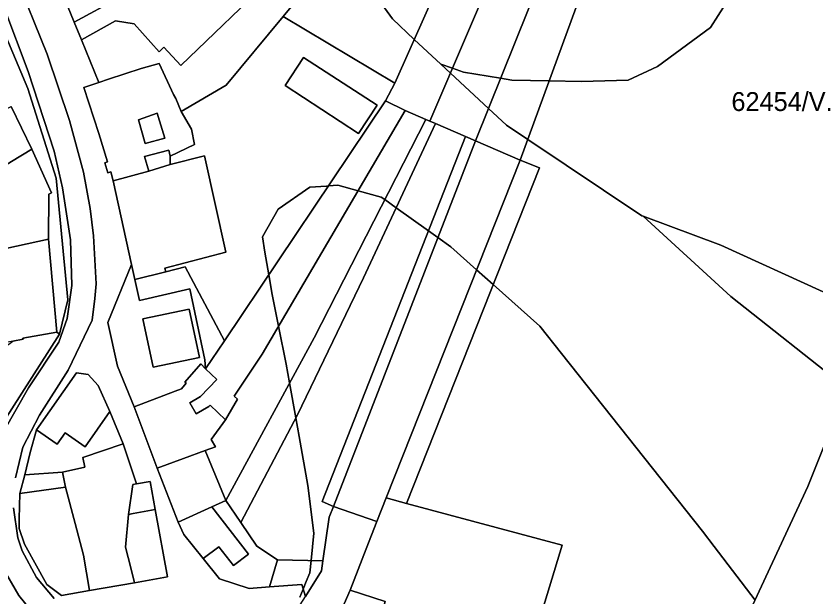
# Model space of a CAD drawing. Extents: x -522079 to -518833, y -1142400 to -1139961.
# Drawn here: x -520338.9 to -520127.5, y -1141173.1 to -1141019.5 of the extents above; entities that cross this region are included whole.
import ezdxf

# ---------------------------------------------------------------- set-up
doc = ezdxf.new("R2010")
doc.units = 0
for name, color, linetype in [('95560013', 7, 'Continuous'), ('95590013', 7, 'Continuous'), ('95640013', 7, 'Continuous'), ('95660013', 7, 'Continuous')]:
    doc.layers.add(name, color=color, linetype=linetype)

msp = doc.modelspace()

# ---------------------------------------------------------------- linework, layer by layer
at = {"layer": '95560013'}
for points in [[(-520205.51, -1141057.7), (-520170.88, -1140963.13), (-520079.53, -1141019.58), (-520129.38, -1141144.09), (-520158.56, -1141206.98), (-520178.85, -1141202.22), (-520209, -1141207.86), (-520194.38, -1141159.65), (-520235.62, -1141148.58), (-520200.4, -1141059.73)], [(-520079.53, -1141019.58), (-520032.33, -1141047.7), (-519951.21, -1141077.01), (-519948.1, -1141084.44), (-519980.55, -1141165.39), (-520014.17, -1141252.24), (-520020.92, -1141254.2), (-520158.56, -1141206.98), (-520129.38, -1141144.09)]]:
    msp.add_lwpolyline(points, close=True, dxfattribs=at)
at = {"layer": '95590013'}
for points in [[(-520278.46, -1140964.1), (-520294.61, -1140946.2), (-520299.04, -1140950.24), (-520300.74, -1140948.36), (-520257.36, -1140921.21), (-520246.32, -1140932.55), (-520237.12, -1140923.52), (-520250.18, -1140910.34), (-520199.46, -1140857.65), (-520181.95, -1140869.32), (-520182.55, -1140869.96), (-520164.55, -1140881.96), (-520151.68, -1140896.26), (-520156.19, -1140899.86), (-520180.26, -1140950.09), (-520199.25, -1140950.43), (-520200.79, -1140952.24), (-520238.67, -1141037.33), (-520268.23, -1141019.69), (-520245.17, -1140991.88)], [(-520235.95, -1141044.56), (-520241.17, -1141042.05), (-520238.67, -1141037.33), (-520200.79, -1140952.24), (-520189.01, -1140952.86), (-520229.4, -1141047.39), (-520230.46, -1141046.93)], [(-520181.77, -1140953.24), (-520178.74, -1140956.58), (-520217.35, -1141052.59), (-520219.97, -1141051.46), (-520227.89, -1141048.04), (-520229.4, -1141047.39), (-520189.01, -1140952.86)], [(-520217.35, -1141052.59), (-520178.74, -1140956.58), (-520175.23, -1140960.44), (-520170.88, -1140963.13), (-520205.51, -1141057.7)], [(-520291.66, -1141053.56), (-520292.48, -1141049.55), (-520295.18, -1141044.79), (-520283.27, -1141037.84), (-520268.23, -1141019.69), (-520238.67, -1141037.33), (-520241.17, -1141042.05), (-520283.75, -1141105.56), (-520294.2, -1141085.93), (-520299.29, -1141087.24), (-520299.54, -1141086.27), (-520283.36, -1141082.1), (-520289.01, -1141056.56), (-520298.12, -1141058.85), (-520298.11, -1141056.69)], [(-520262.81, -1141030.49), (-520267.66, -1141037.99), (-520248.33, -1141050.65), (-520243.34, -1141043.16)], [(-520280.3, -1141121.02), (-520283.49, -1141126.48), (-520287.59, -1141122.55), (-520287.92, -1141122.9), (-520291.23, -1141124.89), (-520292.95, -1141121.95), (-520290.1, -1141120.29), (-520285.76, -1141115.8), (-520288.75, -1141112.92), (-520283.75, -1141105.56), (-520241.17, -1141042.05), (-520235.95, -1141044.56), (-520273.79, -1141109.04), (-520281.17, -1141120.23)], [(-520288.84, -1141134.57), (-520286.17, -1141133.59), (-520287.28, -1141131.69), (-520283.49, -1141126.48), (-520280.3, -1141121.02), (-520281.17, -1141120.23), (-520273.79, -1141109.04), (-520235.95, -1141044.56), (-520230.46, -1141046.93), (-520260.05, -1141104.78), (-520283.41, -1141147.79)], [(-520229.4, -1141047.39), (-520227.89, -1141048.04), (-520246.96, -1141088.89), (-520264.44, -1141125.14), (-520279.46, -1141153.62), (-520283.41, -1141147.79), (-520260.05, -1141104.78), (-520230.46, -1141046.93)], [(-520264.44, -1141125.14), (-520246.96, -1141088.89), (-520227.89, -1141048.04), (-520219.97, -1141051.46), (-520257.88, -1141148.13), (-520254.95, -1141149.39), (-520256.03, -1141152.27), (-520257.71, -1141163.82), (-520269.77, -1141163.56), (-520275.19, -1141159.91), (-520279.46, -1141153.62)], [(-520205.51, -1141057.7), (-520240.94, -1141147.15), (-520243.41, -1141153.37), (-520254.95, -1141149.39), (-520217.35, -1141052.59)], [(-520200.4, -1141059.73), (-520235.62, -1141148.58), (-520240.94, -1141147.15), (-520205.51, -1141057.7)], [(-520309.19, -1141151.52), (-520308.03, -1141143.58), (-520307.07, -1141143.41), (-520303.47, -1141142.76), (-520302.11, -1141150.23), (-520307.91, -1141151.29)], [(-520275.19, -1141159.91), (-520269.77, -1141163.56), (-520271.87, -1141170.72), (-520277.22, -1141171.12), (-520285.07, -1141168.6), (-520289.43, -1141163.17), (-520285.21, -1141160.06), (-520281.38, -1141165.06), (-520277.44, -1141162.04), (-520287.07, -1141149.47), (-520283.41, -1141147.79), (-520279.46, -1141153.62)], [(-520209, -1141207.86), (-520222.29, -1141209.66), (-520219.73, -1141201.41), (-520215.84, -1141187.57), (-520242.23, -1141179.94), (-520242.77, -1141179.78), (-520241.26, -1141174.54), (-520250.48, -1141171.53), (-520246.26, -1141160.66), (-520243.41, -1141153.37), (-520240.94, -1141147.15), (-520235.62, -1141148.58), (-520194.38, -1141159.65)], [(-520243.41, -1141153.37), (-520246.26, -1141160.66), (-520250.48, -1141171.53), (-520253.97, -1141179.43), (-520255.51, -1141182.9), (-520257.33, -1141187.03), (-520257.63, -1141187.7), (-520267.83, -1141182.58), (-520262.19, -1141185.29), (-520260.45, -1141181.87), (-520258.53, -1141178.07), (-520263.7, -1141175.46), (-520262.34, -1141173.28), (-520258.09, -1141166.43), (-520257.71, -1141163.82), (-520256.03, -1141152.27), (-520254.95, -1141149.39)], [(-520241.26, -1141174.54), (-520242.77, -1141179.78), (-520243.9, -1141183.68), (-520253.97, -1141179.43), (-520250.48, -1141171.53)]]:
    msp.add_lwpolyline(points, close=True, dxfattribs=at)
msp.add_lwpolyline([(-520245.17, -1140991.88), (-520268.23, -1141019.69), (-520283.27, -1141037.84), (-520295.18, -1141044.79), (-520296.61, -1141041.42), (-520297.24, -1141040.29), (-520301.05, -1141032.14), (-520305.82, -1141033.42), (-520314.43, -1141036.29), (-520317.01, -1141037.16), (-520321.6, -1141025.87), (-520312.58, -1141020.86), (-520307.7, -1141021.63), (-520301.02, -1141029.07), (-520299.78, -1141027.82), (-520295.32, -1141032.65), (-520270.67, -1141008.89)], dxfattribs=at)
at = {"layer": '95640013'}
for points in [[(-520371.53, -1140953.82), (-520335.76, -1141038.73), (-520328.34, -1141062.52), (-520325.25, -1141094.67), (-520327.42, -1141103.8), (-520328.09, -1141103.27), (-520330.35, -1141078.64), (-520330.22, -1141066.74), (-520329.51, -1141066.36), (-520334.74, -1141054.84), (-520340.18, -1141043.47)], [(-520344.78, -1141130.88), (-520327.42, -1141103.8), (-520325.25, -1141094.67), (-520328.34, -1141062.52), (-520335.76, -1141038.73), (-520371.53, -1140953.82)], [(-520339.2, -1141008.34), (-520330.66, -1141029.65), (-520324.76, -1141047.17), (-520321.07, -1141060.89), (-520319.27, -1141070.53), (-520318.44, -1141077.73), (-520317.76, -1141090.48), (-520318.04, -1141094.37), (-520318.78, -1141100.08), (-520325.12, -1141113.35), (-520332.74, -1141125.19), (-520337.15, -1141133.73), (-520339.09, -1141141.84)], [(-520339.09, -1141141.84), (-520337.15, -1141133.73), (-520332.74, -1141125.19), (-520325.12, -1141113.35), (-520318.78, -1141100.08), (-520318.04, -1141094.37), (-520317.76, -1141090.48), (-520318.44, -1141077.73), (-520319.27, -1141070.53), (-520321.07, -1141060.89), (-520324.76, -1141047.17), (-520330.66, -1141029.65), (-520339.2, -1141008.34)], [(-520328.8, -1141008.12), (-520323.52, -1141021.14), (-520321.6, -1141025.87), (-520317.01, -1141037.16), (-520320.97, -1141038.48), (-520317.05, -1141050.62), (-520314.7, -1141058.15), (-520315.46, -1141058.39), (-520314.63, -1141061.07), (-520313.88, -1141060.82), (-520313.18, -1141063.23), (-520308.39, -1141085.31), (-520314.66, -1141100.66), (-520312.08, -1141112.23), (-520307.67, -1141123.05), (-520305.82, -1141127.93), (-520301.56, -1141139.26), (-520296.03, -1141153.59), (-520294.54, -1141156.83), (-520289.43, -1141163.17), (-520285.07, -1141168.6), (-520277.22, -1141171.12), (-520271.87, -1141170.72), (-520263.33, -1141170.08), (-520262.34, -1141173.28)], [(-520342.14, -1141129.51), (-520335.59, -1141118), (-520327.56, -1141105.89), (-520325.35, -1141099.6), (-520324.16, -1141090.88), (-520324.51, -1141078.81), (-520326.63, -1141065), (-520328.86, -1141055.37), (-520335.75, -1141034.28), (-520342.18, -1141017.11)], [(-520342.18, -1141017.11), (-520335.75, -1141034.28), (-520328.86, -1141055.37), (-520326.63, -1141065), (-520324.51, -1141078.81), (-520324.16, -1141090.88), (-520325.35, -1141099.6), (-520327.56, -1141105.89), (-520335.59, -1141118), (-520342.14, -1141129.51)], [(-520425.27, -1141175.41), (-520408.18, -1141157.48), (-520397.97, -1141139.24), (-520387.46, -1141120.02), (-520366.58, -1141115.24), (-520361.02, -1141115.3), (-520345.24, -1141109.63), (-520339.78, -1141105.62), (-520337.04, -1141105.09), (-520337.09, -1141104.85), (-520328.09, -1141103.27), (-520327.42, -1141103.8), (-520344.78, -1141130.88), (-520344.38, -1141136.25), (-520345.84, -1141145.82), (-520345.14, -1141156.25), (-520343.69, -1141161.58), (-520342.68, -1141165.24), (-520338.22, -1141172.95), (-520335.19, -1141176.69)], [(-520339.64, -1141149.76), (-520338.41, -1141157.75), (-520337.34, -1141161.13), (-520333.5, -1141168.21), (-520328.85, -1141173.77)], [(-520328.85, -1141173.77), (-520333.5, -1141168.21), (-520337.34, -1141161.13), (-520338.41, -1141157.75), (-520339.64, -1141149.76)], [(-520335.19, -1141176.69), (-520338.22, -1141172.95), (-520342.68, -1141165.24)]]:
    msp.add_lwpolyline(points, dxfattribs=at)
for points in [[(-520310.61, -1141006.67), (-520315.31, -1141011.02), (-520311.83, -1141014.78), (-520323.52, -1141021.14), (-520328.8, -1141008.12), (-520322.15, -1141002.36), (-520288.83, -1140973.5), (-520288.51, -1140973.21), (-520285.91, -1140975.7), (-520297.15, -1140986.51), (-520314.09, -1141002.81)], [(-520261.15, -1140992.05), (-520264.81, -1140995.88), (-520260.98, -1140999.54), (-520270.67, -1141008.89), (-520295.32, -1141032.65), (-520299.78, -1141027.82), (-520301.02, -1141029.07), (-520307.7, -1141021.63), (-520312.58, -1141020.86), (-520321.6, -1141025.87), (-520323.52, -1141021.14), (-520311.83, -1141014.78), (-520315.31, -1141011.02), (-520310.61, -1141006.67), (-520314.09, -1141002.81), (-520297.15, -1140986.51), (-520285.91, -1140975.7), (-520279.41, -1140981.92), (-520275.75, -1140978.09)], [(-520262.81, -1141030.49), (-520243.34, -1141043.16), (-520248.33, -1141050.65), (-520267.66, -1141037.99)], [(-520317.05, -1141050.62), (-520320.97, -1141038.48), (-520317.01, -1141037.16), (-520314.43, -1141036.29), (-520305.82, -1141033.42), (-520301.05, -1141032.14), (-520297.24, -1141040.29), (-520296.61, -1141041.42), (-520295.18, -1141044.79), (-520292.48, -1141049.55), (-520291.66, -1141053.56), (-520298.11, -1141056.69), (-520298.5, -1141055.07), (-520304.9, -1141056.77), (-520303.8, -1141060.64), (-520313.18, -1141063.23), (-520313.88, -1141060.82), (-520314.63, -1141061.07), (-520315.46, -1141058.39), (-520314.7, -1141058.15)], [(-520348.84, -1141047.55), (-520340.18, -1141043.47), (-520334.74, -1141054.84), (-520340.14, -1141058.06), (-520353.1, -1141065.99), (-520355.55, -1141067.49), (-520365.3, -1141073.88), (-520371.97, -1141078.27), (-520384.48, -1141082.4), (-520390.79, -1141066.51), (-520380.42, -1141062.83), (-520367.77, -1141056.92), (-520360.31, -1141053.23)], [(-520301.57, -1141045.28), (-520306.5, -1141047.04), (-520304.78, -1141053.3), (-520299.56, -1141051.86), (-520300.92, -1141047.3)], [(-520306.5, -1141047.04), (-520301.57, -1141045.28), (-520300.92, -1141047.3), (-520299.56, -1141051.86), (-520304.78, -1141053.3)], [(-520217.35, -1141052.59), (-520254.95, -1141149.39), (-520257.88, -1141148.13), (-520219.97, -1141051.46)], [(-520334.74, -1141054.84), (-520329.51, -1141066.36), (-520330.22, -1141066.74), (-520330.35, -1141078.64), (-520359.41, -1141084.99), (-520360.71, -1141085.77), (-520365.3, -1141073.88), (-520355.55, -1141067.49), (-520353.1, -1141065.99), (-520340.14, -1141058.06)], [(-520298.11, -1141056.69), (-520298.12, -1141058.85), (-520303.8, -1141060.64), (-520304.9, -1141056.77), (-520298.5, -1141055.07)], [(-520308.39, -1141085.31), (-520313.18, -1141063.23), (-520303.8, -1141060.64), (-520298.12, -1141058.85), (-520289.01, -1141056.56), (-520283.36, -1141082.1), (-520299.54, -1141086.27), (-520299.29, -1141087.24), (-520307.52, -1141089.35)], [(-520374.68, -1141099.98), (-520375.66, -1141093.7), (-520374.62, -1141093.47), (-520366.94, -1141090.81), (-520364.74, -1141089.55), (-520364.98, -1141088.31), (-520360.71, -1141085.77), (-520359.41, -1141084.99), (-520330.35, -1141078.64), (-520328.09, -1141103.27), (-520337.09, -1141104.85), (-520337.04, -1141105.09), (-520339.78, -1141105.62), (-520356.84, -1141108.9), (-520357.5, -1141105.49), (-520361.02, -1141115.3), (-520366.58, -1141115.24), (-520368.35, -1141107.89), (-520395.09, -1141114.42), (-520397.79, -1141103.97)], [(-520307.67, -1141123.05), (-520312.08, -1141112.23), (-520314.66, -1141100.66), (-520308.39, -1141085.31), (-520307.52, -1141089.35), (-520306.28, -1141094.87), (-520292.97, -1141091.81), (-520289, -1141110.56), (-520288.75, -1141112.92), (-520290.03, -1141111.68), (-520294.23, -1141116.47), (-520293.88, -1141116.78), (-520295.14, -1141118.22), (-520296.78, -1141118.85)], [(-520283.75, -1141105.56), (-520288.75, -1141112.92), (-520289, -1141110.56), (-520292.97, -1141091.81), (-520306.28, -1141094.87), (-520307.52, -1141089.35), (-520299.29, -1141087.24), (-520294.2, -1141085.93)], [(-520290.35, -1141109.96), (-520293.08, -1141097.17), (-520305.34, -1141099.75), (-520302.64, -1141112.56)], [(-520305.34, -1141099.75), (-520293.08, -1141097.17), (-520290.35, -1141109.96), (-520302.64, -1141112.56)], [(-520301.56, -1141139.26), (-520305.82, -1141127.93), (-520307.67, -1141123.05), (-520296.78, -1141118.85), (-520295.14, -1141118.22), (-520293.88, -1141116.78), (-520294.23, -1141116.47), (-520290.03, -1141111.68), (-520288.75, -1141112.92), (-520285.76, -1141115.8), (-520290.1, -1141120.29), (-520292.95, -1141121.95), (-520291.23, -1141124.89), (-520287.92, -1141122.9), (-520287.59, -1141122.55), (-520283.49, -1141126.48), (-520287.28, -1141131.69), (-520286.17, -1141133.59), (-520288.84, -1141134.57), (-520294.61, -1141136.72)], [(-520333.47, -1141129.1), (-520335.21, -1141135.1), (-520336.61, -1141141.05), (-520337.89, -1141145.94), (-520338.1, -1141152.71), (-520338.08, -1141155.23), (-520336.67, -1141159.38), (-520330.81, -1141170.06), (-520326.87, -1141172.95), (-520319.49, -1141171.67), (-520307.53, -1141169.64), (-520298.87, -1141168.07), (-520302.11, -1141150.23), (-520303.47, -1141142.76), (-520307.07, -1141143.41), (-520310.58, -1141132.78), (-520314.1, -1141124.27), (-520317.19, -1141117.39), (-520319.83, -1141114.42), (-520322.89, -1141113.99)], [(-520328.05, -1141132.9), (-520333.47, -1141129.1), (-520322.89, -1141113.99), (-520319.83, -1141114.42), (-520317.19, -1141117.39), (-520314.1, -1141124.27), (-520320.65, -1141133.62), (-520325.95, -1141129.91)], [(-520326.63, -1141140.31), (-520336.61, -1141141.05), (-520335.21, -1141135.1), (-520333.47, -1141129.1), (-520328.05, -1141132.9), (-520325.95, -1141129.91), (-520320.65, -1141133.62), (-520314.1, -1141124.27), (-520310.58, -1141132.78), (-520321.22, -1141136.45), (-520320.69, -1141138.98)], [(-520320.69, -1141138.98), (-520321.22, -1141136.45), (-520310.58, -1141132.78), (-520307.07, -1141143.41), (-520308.03, -1141143.58), (-520309.19, -1141151.52), (-520309.97, -1141160.19), (-520308.56, -1141165.63), (-520307.53, -1141169.64), (-520319.49, -1141171.67), (-520321.08, -1141162.3), (-520323.24, -1141153.9), (-520325.8, -1141144.31), (-520326.63, -1141140.31)], [(-520283.41, -1141147.79), (-520287.07, -1141149.47), (-520296.03, -1141153.59), (-520301.56, -1141139.26), (-520294.61, -1141136.72), (-520288.84, -1141134.57)], [(-520337.89, -1141145.94), (-520336.61, -1141141.05), (-520326.63, -1141140.31), (-520325.8, -1141144.31)], [(-520319.49, -1141171.67), (-520326.87, -1141172.95), (-520330.81, -1141170.06), (-520336.67, -1141159.38), (-520338.08, -1141155.23), (-520338.1, -1141152.71), (-520337.89, -1141145.94), (-520325.8, -1141144.31), (-520323.24, -1141153.9), (-520321.08, -1141162.3)], [(-520309.19, -1141151.52), (-520307.91, -1141151.29), (-520302.11, -1141150.23), (-520298.87, -1141168.07), (-520307.53, -1141169.64), (-520308.56, -1141165.63), (-520309.97, -1141160.19)], [(-520296.03, -1141153.59), (-520287.07, -1141149.47), (-520277.44, -1141162.04), (-520281.38, -1141165.06), (-520285.21, -1141160.06), (-520289.43, -1141163.17), (-520294.54, -1141156.83)], [(-520269.77, -1141163.56), (-520257.71, -1141163.82), (-520258.09, -1141166.43), (-520262.34, -1141173.28), (-520263.33, -1141170.08), (-520271.87, -1141170.72)]]:
    msp.add_lwpolyline(points, close=True, dxfattribs=at)
at = {"layer": '95660013'}
for points in [[(-520253.02, -1141001.35), (-520239.33, -1141020.32), (-520233.52, -1141025.76), (-520226.54, -1141032.29), (-520223.97, -1141034.69), (-520213.91, -1141044.05), (-520209.15, -1141048.48), (-520203.51, -1141052.25), (-520173.32, -1141072.44), (-520172.96, -1141072.58), (-520149.72, -1141093.77), (-520118.98, -1141118.13)], [(-520149.01, -1141012.96), (-520155.09, -1141022.62), (-520169.13, -1141032.93), (-520176.88, -1141036.5), (-520189.25, -1141036.92), (-520197.83, -1141036.73), (-520207.68, -1141036.5), (-520210.68, -1141036.01), (-520220.47, -1141034.4), (-520223.41, -1141033.38), (-520226.54, -1141032.29), (-520233.52, -1141025.76), (-520239.33, -1141020.32), (-520253.02, -1141001.35)], [(-520125.34, -1141092.62), (-520152.37, -1141080.22), (-520172.96, -1141072.58), (-520173.32, -1141072.44), (-520203.51, -1141052.25), (-520209.15, -1141048.48), (-520213.91, -1141044.05), (-520223.97, -1141034.69), (-520226.54, -1141032.29), (-520223.41, -1141033.38), (-520220.47, -1141034.4), (-520210.68, -1141036.01), (-520207.68, -1141036.5), (-520197.83, -1141036.73), (-520189.25, -1141036.92), (-520176.88, -1141036.5), (-520169.13, -1141032.93), (-520155.09, -1141022.62), (-520149.01, -1141012.96)], [(-520263.83, -1141173.4), (-520262.95, -1141171.3), (-520262.1, -1141169.26), (-520261.14, -1141166.96), (-520260.82, -1141163.75), (-520260.09, -1141156.44), (-520261.66, -1141143.81), (-520263.98, -1141130.92), (-520264.87, -1141125.95), (-520266.53, -1141116.71), (-520267.43, -1141111.71), (-520269.44, -1141101.63), (-520271.1, -1141093.29), (-520272, -1141088.04), (-520273.04, -1141082.04), (-520273.73, -1141078.03), (-520269.53, -1141070.66), (-520261.14, -1141064.87), (-520256.72, -1141064.56), (-520256.23, -1141064.52), (-520253.79, -1141064.34), (-520248.42, -1141065.81), (-520242.25, -1141067.5), (-520241.32, -1141068.17), (-520238.3, -1141070.33), (-520229.77, -1141076.44), (-520227.3, -1141078.21), (-520223.89, -1141080.66), (-520217.03, -1141086.78), (-520212.66, -1141090.67), (-520200.28, -1141101.71), (-520194.6, -1141108.87), (-520157.27, -1141155.91), (-520154.17, -1141159.99), (-520143.35, -1141174.2)], [(-520143.35, -1141174.2), (-520154.17, -1141159.99), (-520157.27, -1141155.91), (-520194.6, -1141108.87), (-520200.28, -1141101.71), (-520212.66, -1141090.67), (-520217.03, -1141086.78), (-520223.89, -1141080.66), (-520227.3, -1141078.21), (-520229.77, -1141076.44), (-520238.3, -1141070.33), (-520241.32, -1141068.17), (-520242.25, -1141067.5), (-520248.42, -1141065.81), (-520253.79, -1141064.34), (-520256.23, -1141064.52), (-520256.72, -1141064.56), (-520261.14, -1141064.87), (-520269.53, -1141070.66), (-520273.73, -1141078.03), (-520273.04, -1141082.04), (-520272, -1141088.04), (-520271.1, -1141093.29), (-520269.44, -1141101.63), (-520267.43, -1141111.71), (-520266.53, -1141116.71), (-520264.87, -1141125.95), (-520263.98, -1141130.92), (-520261.66, -1141143.81), (-520260.09, -1141156.44), (-520260.82, -1141163.75), (-520261.14, -1141166.96), (-520262.1, -1141169.26), (-520262.95, -1141171.3), (-520263.83, -1141173.4)], [(-520118.98, -1141118.13), (-520149.72, -1141093.77), (-520172.96, -1141072.58), (-520152.37, -1141080.22), (-520125.34, -1141092.62)]]:
    msp.add_lwpolyline(points, dxfattribs=at)

# ---------------------------------------------------------------- texts
msp.add_text('62454/V.', height=5, rotation=0, dxfattribs=at).set_placement((-520149.59, -1141044.7))

doc.saveas('drawing.dxf')
